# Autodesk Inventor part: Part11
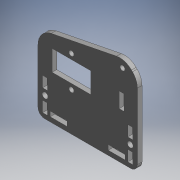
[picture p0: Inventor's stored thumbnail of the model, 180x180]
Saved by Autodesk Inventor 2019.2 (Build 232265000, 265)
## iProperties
Part Number: Part11
Material: Generic
Document SubType Name: Modeling
Designer: richard.girt
Mass: 6.87981 g
Surface Area: 62.6223 cm^2
Volume: 6.87981 cm^3
Density: 1 g/cm^3
Appearance: Default
Author: richard.girt
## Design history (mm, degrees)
sketch "Sketch1"
  geometry: L1 (-30, 0)-(30, 0); L2 (30, 0)-(30, 48.071); L3 (-30, 43.214)-(-30, 0); L4 (-21.5, 39)-(1.9, 39); L5 (1.9, 39)-(1.9, 26.5); L6 (1.9, 26.5)-(-21.5, 26.5); L7 (-21.5, 26.5)-(-21.5, 39); L8 (-22.6, 5.7)-(-12.4, 5.7); L9 (-12.4, 5.7)-(-12.4, 2.7); L10 (-12.4, 2.7)-(-22.6, 2.7); L11 (-22.6, 2.7)-(-22.6, 5.7); L12 (19, 37)-(22, 37); L13 (22, 37)-(22, 27.75); L14 (22, 27.75)-(19, 27.75); L15 (19, 27.75)-(19, 37); L16 (12.4, 5.7)-(22.6, 5.7); L17 (22.6, 5.7)-(22.6, 2.7); L18 (22.6, 2.7)-(12.4, 2.7); L19 (12.4, 2.7)-(12.4, 5.7); L20 (-30, 43.214)-(22.569, 55.502); L21 (22.569, 55.502)-(30, 48.071); L22 (-12.4, 4.2)-(12.4, 4.2); 4 further points
  constraints: 44 end point, 9 parallel, 6 perpendicular, 5 horizontal, 4 midpoint, 2 collinear, 1 coincident, 1 vertical alignment
  dimensions: "d0" = 60 distance of L1.start L1.end; "d1" = 43.214 distance of L3.start L1.start; "d2" = 23.4 distance of L4.start L4.end; "d3" = 12.5 distance of L4.end L5.end; "d4" = 8.5 distance between parallel lines of L3 L7; "d6" = 3 distance of L12.start L12.end; "d8" = 8 distance between parallel lines of L2 L13; "d9" = 9.25 distance of L12.end L13.end; "d10" = 10.2 distance of L9.end L10.end; "d11" = 10.2 distance of L17.end L18.end (= d10); "d14" = 2.7 distance between parallel lines of L18 L1; "d33" = 37 distance between parallel lines of L1 L12; "d34" = 26.5 distance between parallel lines of L1 L6; "d35" = 50 distance from line of L1 point (21, 50); "d36" = 9 distance from line of L2 point (21, 50); "d38" = 5 distance from line of L20 point (21, 50); "d39" = 5 distance from line of L21 point (21, 50); "d40" = 45 deg angle of L2 L21; "d41" = 24.8 distance of L22.start L22.end
extrude "Extrusion1" new body sketch "Sketch1" distance "d15" = 2.8; taper "d16" = 0 deg
sketch "Sketch2"
  geometry: L1 (30, 0)-(30, 48.071) reference; L2 (-30, 43.214)-(-30, 0) reference; L3 (-27.3, 21.9)-(-24.3, 21.9); L4 (-24.3, 21.9)-(-24.3, 15.7); L5 (-24.3, 15.7)-(-27.3, 15.7); L6 (-27.3, 15.7)-(-27.3, 21.9); L7 (-27.3, 8.9)-(-24.3, 8.9); L8 (-24.3, 8.9)-(-24.3, 2.7); L9 (-24.3, 2.7)-(-27.3, 2.7); L10 (-27.3, 2.7)-(-27.3, 8.9); L11 (24.3, 2.7)-(27.3, 2.7); L12 (27.3, 2.7)-(27.3, 8.9); L13 (27.3, 8.9)-(24.3, 8.9); L14 (24.3, 8.9)-(24.3, 2.7); L15 (24.3, 15.7)-(27.3, 15.7); L16 (27.3, 15.7)-(27.3, 21.9); L17 (27.3, 21.9)-(24.3, 21.9); L18 (24.3, 21.9)-(24.3, 15.7); L19 (-30, 0)-(30, 0) reference; L20 (25.8, 15.7)-(25.8, 8.9); L21 (-25.8, 15.7)-(-25.8, 8.9); 3 further points
  constraints: 36 end point, 8 parallel, 6 midpoint, 5 equal length, 4 perpendicular, 4 point on line, 3 horizontal, 1 collinear
  dimensions: "d19" = 2.7 distance between parallel lines of L2 L10; "d20" = 2.7 distance between parallel lines of L12 L1; "d49" = 12.3 distance from line of point (25.8, 12.3) L19; "d50" = 3 distance of L11.start L11.end; "d51" = 12.3 distance from line of point (-25.8, 12.3) L19 (derived); "d52" = 6.2 distance of L9.end L7.start; "d53" = 19.2 distance between parallel lines of L3 L9
extrude "Extrusion2" cut sketch "Sketch2" distance "d21" = 2.8; taper "d22" = 0 deg
sketch "Sketch3"
  geometry: L1 (24.3, 8.9)-(27.3, 8.9) reference; L2 (-24.3, 15.7)-(-27.3, 15.7) reference; L3 (-27.3, 8.9)-(-24.3, 8.9) reference; L4 (27.3, 15.7)-(24.3, 15.7) reference; L5 (1.9, 39)-(1.9, 26.5) reference; L6 (-21.5, 39)-(1.9, 39) reference; L7 (-9.8, 42.25)-(-9.8, 32.75); L8 (-9.8, 32.75)-(-9.8, 23.25); L9 (-25.8, 15.7)-(-25.8, 8.9); L10 (25.8, 15.7)-(25.8, 8.9); 8 further points
  constraints: 8 end point, 8 midpoint, 2 coincident, 2 point on line, 1 collinear, 1 horizontal alignment, 1 vertical
  dimensions: "d23" = 19 distance of L8.end L7.start
hole "Hole1" sketch "Sketch3" at (-25.8, 12.3), (25.8, 12.3), (-9.8, 23.25), (-9.8, 42.25), (21, 50) diameter "d24" = 3; stored, may be unused: countersink angle "d28" = 90 deg, drill point angle "d30" = 118 deg; dims "d25" = 6, "d26" = 4, "d27" = 2, "d29" = 8
sketch "Sketch4"
  geometry: C1 r 1.5 at (25.8, 12.3) reference; C2 r 1.5 at (-25.8, 12.3) reference; 3 further points
  constraints: 2 coincident
hole "Hole2" sketch "Sketch4" at (-25.8, 12.3), (25.8, 12.3) diameter "d42" = 3.5; stored, may be unused: countersink angle "d46" = 90 deg, drill point angle "d48" = 118 deg; dims "d43" = 6, "d44" = 4, "d45" = 2, "d47" = 8
fillet "Fillet1" dims "d31" = 4
fillet "Fillet2" dims "d32" = 10
body "Solid1"
